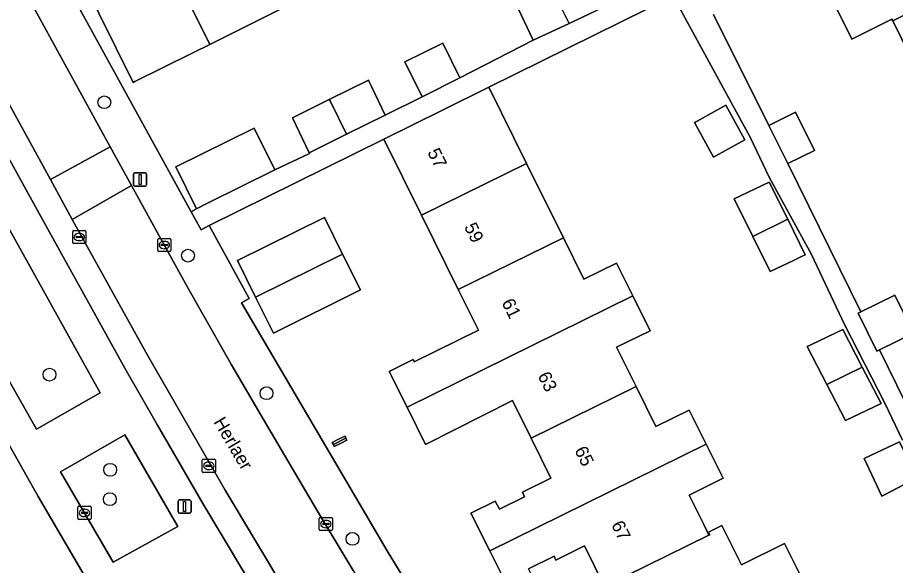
# Model space of a CAD drawing. Extents: x 157793 to 159380, y 380877 to 382313.
# Drawn here: x 158152.9 to 158219.8, y 381505.6 to 381547.4 of the extents above; entities that cross this region are included whole.
import ezdxf

# ---------------------------------------------------------------- set-up
doc = ezdxf.new("R2010")
doc.units = 0
for name, color, linetype in [('IMGEO_Boom', 7, 'Continuous'), ('IMGEO_Erf', 7, 'Continuous'), ('IMGEO_Groenvoorziening', 7, 'Continuous'), ('IMGEO_Kolk', 7, 'Continuous'), ('IMGEO_Lichtmast', 7, 'Continuous'), ('IMGEO_Openbare_ruimte_label', 7, 'Continuous'), ('IMGEO_Pand', 7, 'Continuous'), ('IMGEO_Pand_nummerreeks', 7, 'Continuous'), ('IMGEO_Parkeervlak_open', 7, 'Continuous'), ('IMGEO_Rijbaan_lokaal_open', 7, 'Continuous'), ('IMGEO_Voetpad_open', 7, 'Continuous')]:
    doc.layers.add(name, color=color, linetype=linetype)

msp = doc.modelspace()

# ---------------------------------------------------------------- linework, layer by layer
at = {"layer": 'IMGEO_Boom'}
for centre in [(158159.529, 381540.955), (158165.902, 381529.253), (158155.351, 381520.189), (158171.893, 381518.77), (158159.974, 381512.93), (158159.952, 381510.69), (158178.444, 381507.665)]:
    msp.add_circle(centre, 0.489, dxfattribs=at)
at = {"layer": 'IMGEO_Erf'}
for points in [[(158158.169, 381504.602), (158154.491, 381510.898), (158149.399, 381519.895), (158143.365, 381530.935), (158143.503, 381531.025), (158137.548, 381541.808), (158136.029, 381544.559), (158135.619, 381544.862), (158113.502, 381585.042), (158046.275, 381551.295), (158054.345, 381535.34), (158059.56, 381524.88), (158060.257, 381523.483), (158063.694, 381516.906), (158064.197, 381515.906), (158065.28, 381513.751), (158065.654, 381513.007), (158068.231, 381507.882), (158068.608, 381508.031)], [(158222.402, 381541.527), (158219.62, 381547.158), (158219.556, 381547.288), (158216.498, 381545.777), (158213.685, 381551.469)], [(158156.665, 381549.882), (158166.15, 381532.608), (158166.565, 381532.836), (158164.981, 381536.027), (158170.945, 381538.988), (158172.53, 381535.797), (158175.164, 381537.036), (158175.138, 381537.091), (158173.902, 381539.718), (158173.875, 381539.776), (158176.68, 381541.168), (158179.666, 381542.65), (158179.722, 381542.534), (158179.751, 381542.471), (158179.904, 381542.146), (158180.929, 381539.966), (158183.757, 381541.38), (158182.44, 381544.036), (158185.323, 381545.465), (158186.639, 381542.808), (158192.218, 381545.678), (158190.883, 381548.525)], [(158173.207, 381548.167), (158167.56, 381545.363), (158166.219, 381544.697), (158161.853, 381542.529), (158161.74, 381542.473), (158157.804, 381550.4)], [(158220.367, 381515.18), (158219.018, 381518.02), (158215.949, 381524.008), (158213.428, 381529.336), (158210.202, 381535.25), (158208.758, 381538.302), (158207.134, 381541.279), (158202.879, 381549.08), (158188.826, 381542.116), (158191.716, 381536.284), (158194.518, 381530.629), (158196.086, 381527.464), (158198.577, 381528.697), (158199.812, 381526.204), (158201.133, 381523.537), (158198.58, 381522.273), (158200.058, 381519.288), (158201.572, 381516.232), (158204.113, 381517.49), (158205.402, 381514.888), (158206.692, 381512.285), (158204.106, 381511.004), (158205.222, 381508.751), (158205.476, 381508.238), (158205.616, 381507.956), (158205.673, 381507.984), (158205.578, 381508.178), (158206.609, 381508.687), (158208.099, 381505.678), (158211.379, 381507.303), (158212.789, 381504.457)], [(158205.967, 381547.655), (158210.184, 381539.186), (158212.224, 381540.194), (158213.663, 381537.282), (158211.623, 381536.274), (158217.188, 381524.963), (158219.772, 381526.237), (158221.2, 381523.343), (158218.612, 381522.066), (158221.24, 381516.749)], [(158190.226, 381504.118), (158188.912, 381506.75), (158187.475, 381509.627), (158189.329, 381510.547), (158189.64, 381509.92), (158191.566, 381510.875), (158191.397, 381511.216), (158193.565, 381512.29), (158192.055, 381515.339), (158190.631, 381518.214), (158184.009, 381514.87), (158182.602, 381517.711), (158181.254, 381520.434), (158183.073, 381521.335), (158183.156, 381521.166), (158188.043, 381523.587), (158186.512, 381526.678), (158183.71, 381532.334), (158180.838, 381538.133), (158167.525, 381531.567), (158170.58, 381525.991), (158169.99, 381525.655), (158181.083, 381506.764), (158188.007, 381495.43)], [(158197.657, 381504.028), (158196.125, 381507.123), (158193.957, 381506.049), (158193.811, 381506.345), (158191.865, 381505.385)]]:
    msp.add_lwpolyline(points, dxfattribs=at)
for points in [[(158204.51, 381539.417), (158204.706, 381539.524), (158206.905, 381540.723), (158208.347, 381538.078), (158206.149, 381536.879), (158205.953, 381536.772)], [(158211.617, 381532.029), (158212.959, 381529.32), (158212.62, 381529.16), (158212.064, 381528.897), (158210.274, 381528.05), (158208.954, 381530.716), (158207.532, 381533.587), (158210.216, 381534.857)], [(158177.696, 381529.367), (158179.045, 381526.644), (158172.417, 381523.36), (158171.063, 381526.094), (158169.679, 381528.889), (158176.307, 381532.172)], [(158214.598, 381519.426), (158213.096, 381522.325), (158213.44, 381522.488), (158215.828, 381523.618), (158217.307, 381520.763), (158218.748, 381517.981), (158216.016, 381516.689)], [(158177.95, 381515.345), (158178.027, 381515.189), (158177.591, 381514.973), (158177.061, 381514.711), (158176.986, 381514.863), (158176.909, 381515.018), (158177.439, 381515.281), (158177.875, 381515.497)], [(158217.92, 381514.017), (158220.147, 381515.075), (158221.449, 381512.324), (158219.003, 381511.023), (158218.806, 381510.918), (158217.446, 381513.792)]]:
    msp.add_lwpolyline(points, close=True, dxfattribs=at)
at = {"layer": 'IMGEO_Groenvoorziening'}
for points in [[(158151.956, 381531.901), (158147.028, 381529.224), (158150.968, 381522.006), (158154.352, 381516.038), (158159.211, 381518.799)], [(158161.086, 381515.59), (158156.197, 381512.785), (158160.214, 381505.879), (158165.13, 381508.617)]]:
    msp.add_lwpolyline(points, close=True, dxfattribs=at)
at = {"layer": 'IMGEO_Kolk'}
for p, q in [((158157.118, 381530.256), (158157.118, 381531.108)), ((158157.193, 381531.182), (158158.045, 381531.182)), ((158158.119, 381531.108), (158158.119, 381530.256)), ((158157.377, 381530.676), (158157.377, 381530.688)), ((158157.815, 381530.639), (158157.417, 381530.639)), ((158157.42, 381530.725), (158157.818, 381530.725)), ((158157.606, 381530.962), (158157.631, 381530.962)), ((158157.861, 381530.688), (158157.861, 381530.676)), ((158163.606, 381529.644), (158163.606, 381530.496)), ((158163.681, 381530.57), (158164.533, 381530.57)), ((158164.607, 381530.496), (158164.607, 381529.644)), ((158158.045, 381530.182), (158157.193, 381530.182)), ((158157.629, 381530.402), (158157.604, 381530.402)), ((158163.865, 381530.064), (158163.865, 381530.076)), ((158164.303, 381530.027), (158163.905, 381530.027)), ((158163.908, 381530.113), (158164.306, 381530.113)), ((158164.117, 381529.79), (158164.092, 381529.79)), ((158164.094, 381530.35), (158164.119, 381530.35)), ((158164.349, 381530.076), (158164.349, 381530.064)), ((158164.533, 381529.57), (158163.681, 381529.57)), ((158167.068, 381513.735), (158167.92, 381513.735)), ((158166.993, 381512.809), (158166.993, 381513.661)), ((158167.252, 381513.229), (158167.252, 381513.241)), ((158167.69, 381513.192), (158167.292, 381513.192)), ((158167.295, 381513.278), (158167.693, 381513.278)), ((158167.481, 381513.515), (158167.506, 381513.515)), ((158167.736, 381513.241), (158167.736, 381513.229)), ((158167.994, 381513.661), (158167.994, 381512.809)), ((158167.92, 381512.735), (158167.068, 381512.735)), ((158167.504, 381512.955), (158167.479, 381512.955)), ((158157.52, 381509.221), (158157.52, 381510.073)), ((158157.595, 381510.147), (158158.447, 381510.147)), ((158157.822, 381509.69), (158158.22, 381509.69)), ((158158.008, 381509.927), (158158.033, 381509.927)), ((158158.521, 381510.073), (158158.521, 381509.221)), ((158158.447, 381509.147), (158157.595, 381509.147)), ((158157.779, 381509.641), (158157.779, 381509.653)), ((158158.217, 381509.604), (158157.819, 381509.604)), ((158158.031, 381509.367), (158158.006, 381509.367)), ((158158.263, 381509.653), (158158.263, 381509.641)), ((158175.917, 381508.37), (158175.917, 381509.222)), ((158175.992, 381509.296), (158176.844, 381509.296)), ((158176.405, 381509.076), (158176.43, 381509.076)), ((158176.918, 381509.222), (158176.918, 381508.37)), ((158176.176, 381508.79), (158176.176, 381508.802)), ((158176.614, 381508.753), (158176.216, 381508.753)), ((158176.219, 381508.839), (158176.617, 381508.839)), ((158176.428, 381508.516), (158176.403, 381508.516)), ((158176.66, 381508.802), (158176.66, 381508.79)), ((158176.844, 381508.296), (158175.992, 381508.296))]:
    msp.add_line(p, q, dxfattribs=at)
for points in [[(158157.118, 381530.256), (158157.118, 381531.108)], [(158157.193, 381531.182), (158158.045, 381531.182)], [(158158.119, 381531.108), (158158.119, 381530.256)], [(158163.606, 381529.644), (158163.606, 381530.496)], [(158163.681, 381530.57), (158164.533, 381530.57)], [(158164.607, 381530.496), (158164.607, 381529.644)], [(158158.045, 381530.182), (158157.193, 381530.182)], [(158164.533, 381529.57), (158163.681, 381529.57)], [(158167.068, 381513.735), (158167.92, 381513.735)], [(158166.993, 381512.809), (158166.993, 381513.661)], [(158167.994, 381513.661), (158167.994, 381512.809)], [(158167.92, 381512.735), (158167.068, 381512.735)], [(158157.52, 381509.221), (158157.52, 381510.073)], [(158157.595, 381510.147), (158158.447, 381510.147)], [(158158.521, 381510.073), (158158.521, 381509.221)], [(158158.447, 381509.147), (158157.595, 381509.147)], [(158175.917, 381508.37), (158175.917, 381509.222)], [(158175.992, 381509.296), (158176.844, 381509.296)], [(158176.918, 381509.222), (158176.918, 381508.37)], [(158176.844, 381508.296), (158175.992, 381508.296)]]:
    msp.add_lwpolyline(points, dxfattribs=at)
for centre, radius, start, end in [((158157.195, 381531.106), 0.0765, 91.55205, 178.44795), ((158157.195, 381531.106), 0.0765, 91.55205, 178.44795), ((158158.043, 381531.106), 0.0765, 1.55205, 88.44795), ((158158.043, 381531.106), 0.0765, 1.55205, 88.44795), ((158157.417, 381530.685), 0.0403, 85.87752, 175.75265), ((158157.414, 381530.675), 0.0366, 178.93798, 274.71019), ((158157.818, 381530.682), 0.043, 264.86636, 352.45326), ((158157.822, 381530.687), 0.0386, 1.73085, 96.63898), ((158163.683, 381530.494), 0.0765, 91.55205, 178.44795), ((158163.683, 381530.494), 0.0765, 91.55205, 178.44795), ((158164.531, 381530.494), 0.0765, 1.55205, 88.44795), ((158164.531, 381530.494), 0.0765, 1.55205, 88.44795), ((158157.195, 381530.258), 0.0765, 181.55205, 268.44795), ((158157.195, 381530.258), 0.0765, 181.55205, 268.44795), ((158158.043, 381530.258), 0.0765, 271.55205, 358.44795), ((158158.043, 381530.258), 0.0765, 271.55205, 358.44795), ((158163.905, 381530.073), 0.0403, 85.87752, 175.75265), ((158163.902, 381530.063), 0.0366, 178.93798, 274.71019), ((158164.306, 381530.07), 0.043, 264.86636, 352.45326), ((158164.31, 381530.075), 0.0386, 1.73085, 96.63898), ((158163.683, 381529.646), 0.0765, 181.55205, 268.44795), ((158163.683, 381529.646), 0.0765, 181.55205, 268.44795), ((158164.531, 381529.646), 0.0765, 271.55205, 358.44795), ((158164.531, 381529.646), 0.0765, 271.55205, 358.44795), ((158167.07, 381513.659), 0.0765, 91.55205, 178.44795), ((158167.07, 381513.659), 0.0765, 91.55205, 178.44795), ((158167.918, 381513.659), 0.0765, 1.55205, 88.44795), ((158167.918, 381513.659), 0.0765, 1.55205, 88.44795), ((158167.292, 381513.238), 0.0403, 85.87752, 175.75265), ((158167.289, 381513.228), 0.0366, 178.93798, 274.71019), ((158167.693, 381513.235), 0.043, 264.86636, 352.45326), ((158167.697, 381513.24), 0.0386, 1.73085, 96.63898), ((158167.07, 381512.811), 0.0765, 181.55205, 268.44795), ((158167.07, 381512.811), 0.0765, 181.55205, 268.44795), ((158167.918, 381512.811), 0.0765, 271.55205, 358.44795), ((158167.918, 381512.811), 0.0765, 271.55205, 358.44795), ((158157.597, 381510.071), 0.0765, 91.55205, 178.44795), ((158157.597, 381510.071), 0.0765, 91.55205, 178.44795), ((158157.819, 381509.65), 0.0403, 85.87752, 175.75265), ((158158.224, 381509.652), 0.0386, 1.73085, 96.63898), ((158158.445, 381510.071), 0.0765, 1.55205, 88.44795), ((158158.445, 381510.071), 0.0765, 1.55205, 88.44795), ((158157.597, 381509.223), 0.0765, 181.55205, 268.44795), ((158157.597, 381509.223), 0.0765, 181.55205, 268.44795), ((158157.816, 381509.64), 0.0366, 178.93798, 274.71019), ((158158.22, 381509.647), 0.043, 264.86636, 352.45326), ((158158.445, 381509.223), 0.0765, 271.55205, 358.44795), ((158158.445, 381509.223), 0.0765, 271.55205, 358.44795), ((158175.994, 381509.22), 0.0765, 91.55205, 178.44795), ((158175.994, 381509.22), 0.0765, 91.55205, 178.44795), ((158176.842, 381509.22), 0.0765, 1.55205, 88.44795), ((158176.842, 381509.22), 0.0765, 1.55205, 88.44795), ((158175.994, 381508.372), 0.0765, 181.55205, 268.44795), ((158175.994, 381508.372), 0.0765, 181.55205, 268.44795), ((158176.216, 381508.799), 0.0403, 85.87752, 175.75265), ((158176.213, 381508.789), 0.0366, 178.93798, 274.71019), ((158176.617, 381508.796), 0.043, 264.86636, 352.45326), ((158176.621, 381508.801), 0.0386, 1.73085, 96.63898), ((158176.842, 381508.372), 0.0765, 271.55205, 358.44795), ((158176.842, 381508.372), 0.0765, 271.55205, 358.44795)]:
    msp.add_arc(centre, radius, start, end, dxfattribs=at)
for centre, major_axis, ratio, start_param, end_param in [((158157.605, 381530.682), (-0.387, 0.002), 0.722429, 4.712389, 7.853982), ((158157.63, 381530.682), (-0.39, 0.002), 0.717154, 1.570796, 4.712389), ((158164.093, 381530.07), (-0.387, 0.002), 0.722429, 4.712389, 7.853982), ((158164.118, 381530.07), (-0.39, 0.002), 0.717154, 1.570796, 4.712389), ((158167.48, 381513.235), (-0.387, 0.002), 0.722429, 4.712389, 7.853982), ((158167.505, 381513.235), (-0.39, 0.002), 0.717154, 1.570796, 4.712389), ((158158.007, 381509.647), (-0.387, 0.002), 0.722429, 4.712389, 7.853982), ((158158.032, 381509.647), (-0.39, 0.002), 0.717154, 1.570796, 4.712389), ((158176.404, 381508.796), (-0.387, 0.002), 0.722429, 4.712389, 7.853982), ((158176.429, 381508.796), (-0.39, 0.002), 0.717154, 1.570796, 4.712389)]:
    msp.add_ellipse(centre, major_axis=major_axis, ratio=ratio, start_param=start_param, end_param=end_param, dxfattribs=at)
at = {"layer": 'IMGEO_Lichtmast'}
for p, q in [((158161.76, 381534.666), (158161.76, 381535.466)), ((158161.76, 381535.466), (158161.76, 381534.666)), ((158161.86, 381535.566), (158162.65, 381535.566)), ((158162.65, 381535.566), (158161.86, 381535.566)), ((158162.75, 381535.466), (158162.75, 381534.666)), ((158162.75, 381534.666), (158162.75, 381535.466)), ((158162.65, 381534.566), (158161.86, 381534.566)), ((158161.86, 381534.566), (158162.65, 381534.566)), ((158165.149, 381509.732), (158165.149, 381510.532)), ((158165.149, 381510.532), (158165.149, 381509.732)), ((158165.249, 381510.632), (158166.039, 381510.632)), ((158166.039, 381510.632), (158165.249, 381510.632)), ((158166.139, 381510.532), (158166.139, 381509.732)), ((158166.139, 381509.732), (158166.139, 381510.532)), ((158166.039, 381509.632), (158165.249, 381509.632)), ((158165.249, 381509.632), (158166.039, 381509.632))]:
    msp.add_line(p, q, dxfattribs=at)
for points in [[(158162.18, 381535.441), (158162.33, 381535.441), (158162.33, 381534.691), (158162.18, 381534.691), (158162.18, 381535.441)], [(158165.569, 381510.507), (158165.719, 381510.507), (158165.719, 381509.757), (158165.569, 381509.757), (158165.569, 381510.507)]]:
    msp.add_lwpolyline(points, dxfattribs=at)
for centre, start, end in [((158161.86, 381535.466), 90, 180), ((158161.86, 381535.466), 90, 180), ((158162.65, 381535.466), 0, 90), ((158162.65, 381535.466), 360, 90), ((158161.86, 381534.666), 180, 270), ((158161.86, 381534.666), 180, 270), ((158162.65, 381534.666), 270, 0), ((158162.65, 381534.666), 270, 0), ((158165.249, 381510.532), 90, 180), ((158165.249, 381510.532), 90, 180), ((158166.039, 381510.532), 0, 90), ((158166.039, 381510.532), 360, 90), ((158165.249, 381509.732), 180, 270), ((158165.249, 381509.732), 180, 270), ((158166.039, 381509.732), 270, 0), ((158166.039, 381509.732), 270, 0)]:
    msp.add_arc(centre, 0.1, start, end, dxfattribs=at)
at = {"layer": 'IMGEO_Pand'}
for points in [[(158224.05, 381556.591), (158219.568, 381554.376), (158216.743, 381552.98), (158213.685, 381551.469), (158216.498, 381545.777), (158219.556, 381547.288), (158219.62, 381547.158), (158232.238, 381553.507), (158230.878, 381556.259), (158225.522, 381553.612)], [(158219.62, 381547.158), (158222.402, 381541.527), (158229.702, 381545.17), (158228.253, 381548.103), (158228.114, 381548.385), (158230.078, 381549.356), (158230.217, 381549.074), (158233.602, 381550.746), (158238.986, 381553.406), (158238.84, 381553.702), (158238.643, 381553.605), (158237.483, 381555.954), (158238.201, 381556.309), (158238.064, 381556.587), (158237.195, 381556.158), (158237.28, 381555.998), (158232.238, 381553.507)], [(158169.274, 381556.095), (158163.638, 381553.297), (158167.56, 381545.363), (158173.207, 381548.167)], [(158157.804, 381550.4), (158161.74, 381542.473), (158161.853, 381542.529), (158166.219, 381544.697), (158167.56, 381545.363), (158163.638, 381553.297)], [(158194.955, 381546.961), (158198.018, 381548.397), (158196.684, 381551.244), (158193.557, 381549.778)], [(158194.955, 381546.961), (158193.557, 381549.778), (158190.883, 381548.525), (158192.218, 381545.678)], [(158182.44, 381544.036), (158183.757, 381541.38), (158186.639, 381542.808), (158185.323, 381545.465)], [(158176.68, 381541.168), (158176.737, 381541.052), (158177.997, 381538.511), (158180.929, 381539.966), (158179.904, 381542.146), (158179.751, 381542.471), (158179.722, 381542.534), (158179.666, 381542.65)], [(158191.716, 381536.284), (158188.826, 381542.116), (158185.319, 381540.353), (158180.838, 381538.133), (158183.71, 381532.334)], [(158176.68, 381541.168), (158173.875, 381539.776), (158173.902, 381539.718), (158175.138, 381537.091), (158177.997, 381538.511), (158176.737, 381541.052)], [(158204.51, 381539.417), (158205.953, 381536.772), (158206.149, 381536.879), (158208.347, 381538.078), (158206.905, 381540.723), (158204.706, 381539.524)], [(158210.184, 381539.186), (158211.623, 381536.274), (158213.663, 381537.282), (158212.224, 381540.194)], [(158167.405, 381533.253), (158172.53, 381535.797), (158170.945, 381538.988), (158164.981, 381536.027), (158166.565, 381532.836)], [(158186.512, 381526.678), (158194.518, 381530.629), (158191.716, 381536.284), (158183.71, 381532.334)], [(158208.954, 381530.716), (158211.617, 381532.029), (158210.216, 381534.857), (158207.532, 381533.587)], [(158171.063, 381526.094), (158177.696, 381529.367), (158176.307, 381532.172), (158169.679, 381528.889)], [(158211.617, 381532.029), (158208.954, 381530.716), (158210.274, 381528.05), (158212.064, 381528.897), (158212.62, 381529.16), (158212.959, 381529.32)], [(158186.512, 381526.678), (158188.043, 381523.587), (158183.156, 381521.166), (158183.073, 381521.335), (158181.254, 381520.434), (158182.602, 381517.711), (158199.812, 381526.204), (158198.577, 381528.697), (158196.086, 381527.464), (158194.518, 381530.629)], [(158171.063, 381526.094), (158172.417, 381523.36), (158179.045, 381526.644), (158177.696, 381529.367)], [(158192.055, 381515.339), (158200.058, 381519.288), (158198.58, 381522.273), (158201.133, 381523.537), (158199.812, 381526.204), (158182.602, 381517.711), (158184.009, 381514.87), (158190.631, 381518.214)], [(158217.188, 381524.963), (158216.992, 381524.866), (158218.42, 381521.971), (158218.612, 381522.066), (158221.2, 381523.343), (158219.772, 381526.237)], [(158214.598, 381519.426), (158217.307, 381520.763), (158215.828, 381523.618), (158213.44, 381522.488), (158213.096, 381522.325)], [(158217.307, 381520.763), (158214.598, 381519.426), (158216.016, 381516.689), (158218.748, 381517.981)], [(158192.055, 381515.339), (158193.565, 381512.29), (158191.397, 381511.216), (158191.566, 381510.875), (158189.64, 381509.92), (158189.329, 381510.547), (158187.475, 381509.627), (158188.912, 381506.75), (158205.402, 381514.888), (158204.113, 381517.49), (158201.572, 381516.232), (158200.058, 381519.288)], [(158176.986, 381514.863), (158177.95, 381515.345), (158177.875, 381515.497), (158177.439, 381515.281), (158176.909, 381515.018)], [(158177.95, 381515.345), (158176.986, 381514.863), (158177.061, 381514.711), (158177.591, 381514.973), (158178.027, 381515.189)], [(158220.147, 381515.075), (158217.92, 381514.017), (158217.446, 381513.792), (158218.806, 381510.918), (158219.003, 381511.023), (158221.449, 381512.324)], [(158205.616, 381507.956), (158205.476, 381508.238), (158205.222, 381508.751), (158204.106, 381511.004), (158206.692, 381512.285), (158205.402, 381514.888), (158188.912, 381506.75), (158190.226, 381504.118), (158192.073, 381504.963), (158191.865, 381505.385), (158193.811, 381506.345), (158193.957, 381506.049), (158196.125, 381507.123), (158197.657, 381504.028)], [(158212.789, 381504.457), (158211.379, 381507.303), (158208.099, 381505.678), (158206.609, 381508.687), (158205.578, 381508.178), (158205.673, 381507.984), (158205.616, 381507.956), (158197.657, 381504.028), (158199.076, 381501.163), (158196.733, 381500), (158189.601, 381496.459), (158190.983, 381493.696), (158203.757, 381500)]]:
    msp.add_lwpolyline(points, close=True, dxfattribs=at)
at = {"layer": 'IMGEO_Parkeervlak_open'}
for points in [[(158211.021, 381445.909), (158206.462, 381452.438), (158198.314, 381464.433), (158189.837, 381477.355), (158181.714, 381490.043), (158173.283, 381503.774), (158168.753, 381511.382), (158162.831, 381521.68), (158157.089, 381532.018), (158155.415, 381535.054), (158148.825, 381547.056)], [(158148.449, 381543.56), (158152.339, 381536.528), (158154.693, 381532.233), (158161.1, 381520.669), (158163.584, 381516.344), (158167.051, 381510.356), (158171.612, 381502.714), (158176.956, 381493.981), (158180.068, 381488.973), (158188.156, 381476.274), (158191.493, 381471.166), (158196.6, 381463.411), (158207.708, 381447.175)]]:
    msp.add_lwpolyline(points, dxfattribs=at)
at = {"layer": 'IMGEO_Rijbaan_lokaal_open'}
for points in [[(158148.739, 381547.289), (158148.825, 381547.056), (158155.415, 381535.054), (158159.97, 381537.562), (158153.644, 381549.128)], [(158178.499, 381505.249), (158175.691, 381509.903), (158171.659, 381516.762), (158169.218, 381520.936), (158165.872, 381526.867), (158163.996, 381530.272), (158161.594, 381534.598), (158157.089, 381532.018), (158162.831, 381521.68), (158168.753, 381511.382), (158173.283, 381503.774)]]:
    msp.add_lwpolyline(points, dxfattribs=at)
msp.add_lwpolyline([(158161.594, 381534.598), (158159.97, 381537.562), (158155.415, 381535.054), (158157.089, 381532.018)], close=True, dxfattribs=at)
at = {"layer": 'IMGEO_Voetpad_open'}
for points in [[(158181.083, 381506.764), (158169.99, 381525.655), (158170.58, 381525.991), (158167.525, 381531.567), (158166.905, 381531.233), (158166.15, 381532.608), (158156.665, 381549.882), (158156.798, 381549.969), (158156.228, 381551.201), (158153.101, 381557.958)], [(158153.644, 381549.128), (158159.97, 381537.562), (158161.594, 381534.598), (158163.996, 381530.272), (158165.872, 381526.867), (158169.218, 381520.936), (158171.659, 381516.762), (158175.691, 381509.903), (158178.499, 381505.249), (158182.168, 381499.189), (158184.727, 381495.042), (158189.052, 381488.161), (158192.482, 381482.833), (158196.908, 381476.029), (158199.88, 381471.47), (158203.651, 381465.824), (158207.189, 381460.583), (158211.139, 381454.855), (158219.673, 381442.728), (158220.405, 381441.765), (158225.147, 381444.74)], [(158198.018, 381548.397), (158194.955, 381546.961), (158192.218, 381545.678), (158186.639, 381542.808), (158183.757, 381541.38), (158180.929, 381539.966), (158177.997, 381538.511), (158175.138, 381537.091), (158175.164, 381537.036), (158172.53, 381535.797), (158167.405, 381533.253), (158166.565, 381532.836), (158166.15, 381532.608), (158166.905, 381531.233), (158167.525, 381531.567), (158180.838, 381538.133), (158185.319, 381540.353), (158188.826, 381542.116), (158202.879, 381549.08), (158207.134, 381541.279), (158208.758, 381538.302), (158210.202, 381535.25), (158213.428, 381529.336), (158215.949, 381524.008), (158219.018, 381518.02), (158220.367, 381515.18)], [(158148.825, 381547.056), (158148.739, 381547.289), (158147.639, 381546.803), (158144.538, 381545.376), (158150.255, 381534.969), (158145.375, 381532.267), (158139.575, 381542.843), (158137.548, 381541.808), (158143.503, 381531.025), (158143.365, 381530.935), (158149.399, 381519.895), (158154.491, 381510.898), (158158.169, 381504.602)], [(158221.24, 381516.749), (158218.612, 381522.066), (158218.42, 381521.971), (158216.992, 381524.866), (158217.188, 381524.963), (158211.623, 381536.274), (158210.184, 381539.186), (158205.967, 381547.655)], [(158188.156, 381476.274), (158180.068, 381488.973), (158176.956, 381493.981), (158171.612, 381502.714), (158167.051, 381510.356), (158163.584, 381516.344), (158161.1, 381520.669), (158154.693, 381532.233), (158152.339, 381536.528), (158148.449, 381543.56)], [(158220.925, 381445.928), (158215.033, 381454.286), (158215.155, 381454.363), (158213.23, 381457.086), (158213.909, 381457.425), (158210.491, 381462.328), (158209.819, 381462.024), (158202.402, 381473.13), (158195.005, 381484.47), (158193.967, 381486.126), (158193.881, 381486.263), (158194.249, 381486.486), (158193.532, 381487.602), (158190.7, 381492.013), (158191.096, 381492.237), (158188.833, 381495.915), (158188.007, 381495.43), (158181.083, 381506.764)]]:
    msp.add_lwpolyline(points, dxfattribs=at)
for points in [[(158154.352, 381516.038), (158150.968, 381522.006), (158147.028, 381529.224), (158151.956, 381531.901), (158159.211, 381518.799)], [(158160.214, 381505.879), (158156.197, 381512.785), (158161.086, 381515.59), (158165.13, 381508.617)]]:
    msp.add_lwpolyline(points, close=True, dxfattribs=at)

# ---------------------------------------------------------------- texts
at = {"layer": 'IMGEO_Openbare_ruimte_label'}
msp.add_text('Herlaer', height=1, rotation=300.59044, dxfattribs=at).set_placement((158167.817, 381516.582))
at = {"layer": 'IMGEO_Pand_nummerreeks'}
for s, rotation, p in [('57', 296.26387, (158184.133, 381537.149)), ('59', 296.26387, (158186.936, 381531.469)), ('61', 296.26387, (158189.789, 381525.688)), ('63', 296.26387, (158192.542, 381520.109)), ('65', 296.26387, (158195.344, 381514.429)), ('67', 296.26417, (158198.147, 381508.748))]:
    msp.add_text(s, height=1, rotation=rotation, dxfattribs=at).set_placement(p)

doc.saveas('drawing.dxf')
